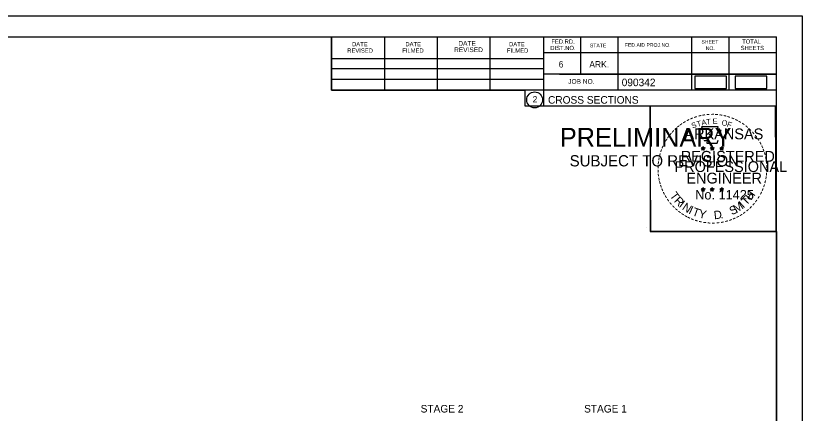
# Model space of a CAD drawing. Extents: x 1370515 to 1370849, y 383299 to 386073.
# Drawn here: x 1370703.4 to 1370848.7, y 385786 to 385859.5 of the extents above; entities that cross this region are included whole.
import ezdxf

# ---------------------------------------------------------------- set-up
doc = ezdxf.new("R2010")
doc.units = 0
for name, color, linetype in [('R_Axis Annot', 7, 'Continuous'), ('R_Border', 7, 'Continuous'), ('R_Border PE', 7, 'Continuous'), ('R_Border Prem', 7, 'Continuous'), ('R_Detour', 7, 'Continuous'), ('R_No Plot', 7, 'Continuous')]:
    doc.layers.add(name, color=color, linetype=linetype)

msp = doc.modelspace()

# ---------------------------------------------------------------- linework, layer by layer
at = {"layer": 'R_Border'}
for p, q in [((1370527.8, 385855.59), (1370843.98, 385855.59)), ((1370761.72, 385845.71), (1370761.72, 385855.59)), ((1370771.58, 385845.71), (1370771.58, 385855.39)), ((1370781.34, 385845.71), (1370781.34, 385855.39)), ((1370791.02, 385845.71), (1370791.02, 385855.39)), ((1370800.88, 385855.59), (1370800.88, 385842.79)), ((1370807.72, 385855.59), (1370807.72, 385848.65)), ((1370814.66, 385855.59), (1370814.66, 385845.71)), ((1370828.24, 385855.59), (1370828.24, 385845.71)), ((1370835.18, 385855.59), (1370835.18, 385845.71)), ((1370843.98, 385650.13), (1370843.98, 385855.59)), ((1370843.98, 385852.65), (1370800.88, 385852.65)), ((1370843.98, 385852.67), (1370843.98, 385852.67)), ((1370761.72, 385851.57), (1370800.88, 385851.57)), ((1370761.72, 385849.71), (1370800.88, 385849.71)), ((1370843.98, 385848.65), (1370800.88, 385848.65)), ((1370803.84, 385848.65), (1370843.98, 385848.65)), ((1370761.72, 385845.71), (1370761.72, 385847.77)), ((1370761.72, 385847.77), (1370800.88, 385847.77)), ((1370843.98, 385845.71), (1370761.72, 385845.71)), ((1370800.88, 385842.79), (1370843.98, 385842.79))]:
    msp.add_line(p, q, dxfattribs=at)
msp.add_circle((1370799.27, 385843.92), 1.47, dxfattribs=at)
at = {"layer": 'R_Border PE'}
for p, q in [((1370830.07, 385835.04), (1370830.42, 385834.93)), ((1370830.07, 385835.04), (1370830.32, 385835)), ((1370830.07, 385835.04), (1370830.3, 385834.92)), ((1370830.2, 385834.63), (1370830.42, 385834.93)), ((1370830.2, 385834.63), (1370830.33, 385834.88)), ((1370830.2, 385834.63), (1370830.41, 385834.85)), ((1370830.42, 385835.3), (1370830.37, 385835.04)), ((1370830.63, 385834.63), (1370830.41, 385834.85)), ((1370830.42, 385834.93), (1370830.42, 385835.3)), ((1370830.42, 385835.3), (1370830.46, 385835.05)), ((1370830.76, 385835.04), (1370830.42, 385834.93)), ((1370830.63, 385834.63), (1370830.42, 385834.93)), ((1370830.76, 385835.04), (1370830.48, 385834.99)), ((1370830.63, 385834.63), (1370830.49, 385834.92)), ((1370830.76, 385835.04), (1370830.56, 385834.94)), ((1370831.74, 385835.04), (1370832.09, 385834.93)), ((1370831.74, 385835.04), (1370831.99, 385835)), ((1370831.74, 385835.04), (1370831.97, 385834.92)), ((1370831.87, 385834.63), (1370832.09, 385834.93)), ((1370831.87, 385834.63), (1370832, 385834.88)), ((1370831.87, 385834.63), (1370832.08, 385834.85)), ((1370832.09, 385835.3), (1370832.04, 385835.04)), ((1370832.3, 385834.63), (1370832.08, 385834.85)), ((1370832.09, 385834.93), (1370832.09, 385835.3)), ((1370832.09, 385835.3), (1370832.13, 385835.05)), ((1370832.43, 385835.04), (1370832.09, 385834.93)), ((1370832.3, 385834.63), (1370832.09, 385834.93)), ((1370832.43, 385835.04), (1370832.15, 385834.99)), ((1370832.3, 385834.63), (1370832.16, 385834.92)), ((1370832.43, 385835.04), (1370832.23, 385834.94)), ((1370833.5, 385835.03), (1370833.85, 385834.92)), ((1370833.5, 385835.03), (1370833.75, 385834.98)), ((1370833.5, 385835.03), (1370833.74, 385834.91)), ((1370833.63, 385834.62), (1370833.85, 385834.92)), ((1370833.63, 385834.62), (1370833.76, 385834.87)), ((1370833.63, 385834.62), (1370833.85, 385834.84)), ((1370833.85, 385835.28), (1370833.81, 385835.03)), ((1370833.85, 385834.92), (1370833.85, 385835.28)), ((1370833.85, 385835.28), (1370833.9, 385835.03)), ((1370834.2, 385835.03), (1370833.85, 385834.92)), ((1370834.06, 385834.62), (1370833.85, 385834.92)), ((1370834.06, 385834.62), (1370833.85, 385834.84)), ((1370834.2, 385835.03), (1370833.91, 385834.98)), ((1370834.06, 385834.62), (1370833.93, 385834.91)), ((1370834.2, 385835.03), (1370833.99, 385834.93)), ((1370830.06, 385827.47), (1370830.41, 385827.36)), ((1370830.06, 385827.47), (1370830.32, 385827.42)), ((1370830.06, 385827.47), (1370830.3, 385827.35)), ((1370830.41, 385827.72), (1370830.37, 385827.47)), ((1370830.41, 385827.36), (1370830.41, 385827.72)), ((1370830.41, 385827.72), (1370830.46, 385827.47)), ((1370830.76, 385827.47), (1370830.41, 385827.36)), ((1370830.76, 385827.47), (1370830.47, 385827.42)), ((1370830.76, 385827.47), (1370830.55, 385827.37)), ((1370831.73, 385827.47), (1370832.08, 385827.36)), ((1370831.73, 385827.47), (1370831.98, 385827.42)), ((1370831.73, 385827.47), (1370831.97, 385827.35)), ((1370832.08, 385827.72), (1370832.04, 385827.47)), ((1370832.08, 385827.36), (1370832.08, 385827.72)), ((1370832.08, 385827.72), (1370832.13, 385827.47)), ((1370832.43, 385827.47), (1370832.08, 385827.36)), ((1370832.43, 385827.47), (1370832.14, 385827.42)), ((1370832.43, 385827.47), (1370832.22, 385827.37)), ((1370833.5, 385827.46), (1370833.85, 385827.35)), ((1370833.5, 385827.46), (1370833.75, 385827.41)), ((1370833.5, 385827.46), (1370833.74, 385827.34)), ((1370833.85, 385827.71), (1370833.81, 385827.46)), ((1370833.85, 385827.35), (1370833.85, 385827.71)), ((1370833.85, 385827.71), (1370833.9, 385827.46)), ((1370834.19, 385827.46), (1370833.85, 385827.35)), ((1370834.19, 385827.46), (1370833.91, 385827.41)), ((1370834.19, 385827.46), (1370833.99, 385827.36)), ((1370830.2, 385827.06), (1370830.41, 385827.36)), ((1370830.2, 385827.06), (1370830.32, 385827.3)), ((1370830.2, 385827.06), (1370830.41, 385827.28)), ((1370830.62, 385827.06), (1370830.41, 385827.36)), ((1370830.62, 385827.06), (1370830.41, 385827.27)), ((1370830.62, 385827.06), (1370830.49, 385827.35)), ((1370831.86, 385827.06), (1370832.08, 385827.36)), ((1370831.86, 385827.06), (1370831.99, 385827.3)), ((1370831.86, 385827.06), (1370832.08, 385827.28)), ((1370832.29, 385827.06), (1370832.08, 385827.36)), ((1370832.29, 385827.06), (1370832.08, 385827.27)), ((1370832.29, 385827.06), (1370832.16, 385827.35)), ((1370833.63, 385827.05), (1370833.85, 385827.35)), ((1370833.63, 385827.05), (1370833.76, 385827.29)), ((1370833.63, 385827.05), (1370833.85, 385827.27)), ((1370834.06, 385827.05), (1370833.85, 385827.35)), ((1370834.06, 385827.05), (1370833.85, 385827.26)), ((1370834.06, 385827.05), (1370833.92, 385827.34))]:
    msp.add_line(p, q, dxfattribs=at)
for points in [[(1370830.11, 385838.92), (1370830.38, 385838.09)], [(1370833.62, 385838), (1370833.76, 385838.28), (1370833.08, 385838.26), (1370833.22, 385838.92), (1370830.11, 385838.92)], [(1370830.6, 385836.5), (1370830.6, 385836.41), (1370831.16, 385836.39), (1370831.11, 385835.92), (1370832.98, 385835.92), (1370833.18, 385836.45)], [(1370830.42, 385835.3), (1370830.63, 385834.63), (1370830.07, 385835.04), (1370830.76, 385835.04), (1370830.2, 385834.63), (1370830.42, 385835.3)], [(1370832.09, 385835.3), (1370832.3, 385834.63), (1370831.74, 385835.04), (1370832.43, 385835.04), (1370831.87, 385834.63), (1370832.09, 385835.3)], [(1370833.85, 385835.28), (1370834.06, 385834.62), (1370833.5, 385835.03), (1370834.2, 385835.03), (1370833.63, 385834.62), (1370833.85, 385835.28)], [(1370830.41, 385827.72), (1370830.62, 385827.06), (1370830.06, 385827.47), (1370830.76, 385827.47), (1370830.2, 385827.06), (1370830.41, 385827.72)], [(1370832.08, 385827.72), (1370832.29, 385827.06), (1370831.73, 385827.47), (1370832.43, 385827.47), (1370831.86, 385827.06), (1370832.08, 385827.72)], [(1370833.85, 385827.71), (1370834.06, 385827.05), (1370833.5, 385827.46), (1370834.19, 385827.46), (1370833.63, 385827.05), (1370833.85, 385827.71)]]:
    msp.add_lwpolyline(points, dxfattribs=at)
for centre, radius in [((1370830.41, 385834.93), 0.172), ((1370830.41, 385834.93), 0.145), ((1370830.41, 385834.93), 0.116), ((1370830.41, 385834.93), 0.0991), ((1370830.41, 385834.93), 0.0747), ((1370830.41, 385834.93), 0.0495), ((1370830.41, 385834.93), 0.0296), ((1370832.08, 385834.93), 0.172), ((1370832.08, 385834.93), 0.145), ((1370832.08, 385834.93), 0.116), ((1370832.08, 385834.93), 0.0991), ((1370832.08, 385834.93), 0.0747), ((1370832.08, 385834.93), 0.0495), ((1370832.08, 385834.93), 0.0296), ((1370833.85, 385834.92), 0.172), ((1370833.85, 385834.92), 0.145), ((1370833.85, 385834.92), 0.116), ((1370833.85, 385834.92), 0.0991), ((1370833.85, 385834.92), 0.0747), ((1370833.85, 385834.92), 0.0495), ((1370833.85, 385834.92), 0.0296), ((1370830.41, 385827.36), 0.172), ((1370830.41, 385827.36), 0.145), ((1370830.41, 385827.36), 0.116), ((1370830.41, 385827.36), 0.0991), ((1370832.08, 385827.36), 0.172), ((1370832.08, 385827.36), 0.145), ((1370832.08, 385827.36), 0.116), ((1370832.08, 385827.36), 0.0991), ((1370833.85, 385827.35), 0.172), ((1370833.85, 385827.35), 0.145), ((1370833.85, 385827.35), 0.116), ((1370833.85, 385827.35), 0.0991), ((1370830.41, 385827.36), 0.0747), ((1370830.41, 385827.36), 0.0495), ((1370830.41, 385827.36), 0.0296), ((1370832.08, 385827.36), 0.0747), ((1370832.08, 385827.36), 0.0495), ((1370832.08, 385827.36), 0.0296), ((1370833.85, 385827.35), 0.0747), ((1370833.85, 385827.35), 0.0495), ((1370833.85, 385827.35), 0.0296)]:
    msp.add_circle(centre, radius, dxfattribs=at)
at = {"layer": 'R_Detour'}
for points in [[(1370828.87, 385846.02), (1370834.7, 385846.02), (1370834.7, 385848.33), (1370828.87, 385848.33)], [(1370836.36, 385846.02), (1370842.19, 385846.02), (1370842.19, 385848.33), (1370836.36, 385848.33)]]:
    msp.add_lwpolyline(points, close=True, dxfattribs=at)
at = {"layer": 'R_No Plot'}
for p, q in [((1370515.4, 385859.48), (1370848.73, 385859.48)), ((1370820.02, 385820.33), (1370820.02, 385820.33))]:
    msp.add_line(p, q, dxfattribs=at)
for points in [[(1370515.39, 385859.48), (1370848.73, 385859.48), (1370848.73, 385646.14), (1370515.39, 385646.14)], [(1370761.72, 385855.59), (1370761.72, 385845.71), (1370797.45, 385845.71), (1370797.45, 385842.79), (1370820.65, 385842.79), (1370820.65, 385819.57), (1370843.98, 385819.57), (1370843.98, 385650.13), (1370527.8, 385650.13), (1370527.8, 385855.59)], [(1370820.65, 385842.82), (1370843.75, 385842.82), (1370843.87, 385819.57), (1370820.77, 385819.57)]]:
    msp.add_lwpolyline(points, close=True, dxfattribs=at)

# ---------------------------------------------------------------- texts
at = {"layer": 'R_Axis Annot'}
for s, p in [('STAGE 2', (1370778.2, 385786.11)), ('STAGE 1', (1370808.41, 385786.11))]:
    msp.add_text(s, height=1.4, dxfattribs=at).set_placement(p)
at = {"layer": 'R_Border'}
for s, height, p in [('FED.RD.', 0.782, (1370802.36, 385854.31)), ('TOTAL', 0.782, (1370837.62, 385854.31)), ('DATE', 0.782, (1370765.52, 385853.83)), ('DATE', 0.782, (1370775.38, 385853.83)), ('REVISED', 0.879, (1370784.38, 385852.75)), ('DATE', 0.879, (1370785.16, 385853.93)), ('DATE', 0.782, (1370794.54, 385853.83)), ('DIST.NO.', 0.782, (1370802.16, 385853.13)), ('STATE', 0.684, (1370809.48, 385853.63)), ('FED.AID PROJ.NO.', 0.684, (1370815.94, 385853.73)), ('SHEET', 0.684, (1370830.1, 385854.31)), ('NO.', 0.684, (1370830.88, 385853.13)), ('SHEETS', 0.782, (1370837.34, 385853.13)), ('REVISED', 0.782, (1370764.64, 385852.65)), ('FILMED', 0.782, (1370774.8, 385852.65)), ('FILMED', 0.782, (1370794.14, 385852.65)), ('6', 1.17, (1370803.72, 385849.91)), ('ARK.', 1.172, (1370809.38, 385849.91)), ('090342', 1.4, (1370815.36, 385846.45)), ('JOB NO.', 0.879, (1370805.48, 385846.89)), ('2', 1.17, (1370798.89, 385843.44)), ('CROSS SECTIONS', 1.4, (1370801.74, 385843.22))]:
    msp.add_text(s, height=height, rotation=360, dxfattribs=at).set_placement(p)
at = {"layer": 'R_Border PE'}
for s, height, rotation, p in [('-', 1.6, 24.3072, (1370828.22, 385839.78)), ('-', 1.6, 19.1761, (1370828.86, 385840.05)), ('-', 1.6, 13.6301, (1370829.61, 385840.29)), ('-', 1.6, 10.2193, (1370830.28, 385840.45)), ('-', 1.6, 5.8968, (1370831.01, 385840.56)), ('-', 1.6, 0.1862, (1370831.78, 385840.63)), ('-', 1.6, 357.743, (1370832.51, 385840.62)), ('-', 1.6, 352.1617, (1370833.25, 385840.56)), ('-', 1.6, 347.2049, (1370833.97, 385840.45)), ('-', 1.6, 342.3362, (1370834.61, 385840.29)), ('-', 1.6, 337.8551, (1370835.34, 385840.07)), ('-', 1.6, 38.9507, (1370825.94, 385838.32)), ('-', 1.6, 36.2317, (1370826.41, 385838.7)), ('-', 1.6, 34.0636, (1370826.99, 385839.09)), ('-', 1.6, 28.7918, (1370827.59, 385839.46)), ('S', 1, 21.594, (1370828.46, 385838.6)), ('T', 1, 16.4036, (1370829.38, 385838.93)), ('A', 1, 11.2132, (1370830.2, 385839.18)), ('T', 1, 6.0228, (1370831.05, 385839.35)), ('E', 1, 0.8323, (1370832.16, 385839.46)), ('O', 1, 350.4515, (1370833.76, 385839.25)), ('F', 1, 340.0707, (1370834.71, 385839.02)), ('-', 1.6, 334.1211, (1370835.97, 385839.8)), ('-', 1.6, 329.6409, (1370836.55, 385839.52)), ('-', 1.6, 325.8627, (1370837.19, 385839.16)), ('-', 1.6, 320.5297, (1370837.8, 385838.73)), ('-', 1.6, 50.6142, (1370824.65, 385836.94)), ('-', 1.6, 48.423, (1370825.06, 385837.42)), ('-', 1.6, 42.9622, (1370825.5, 385837.9)), ('ARKANSAS', 2, 360, (1370826.96, 385836.63)), ('-', 1.6, 315.5786, (1370838.4, 385838.24)), ('-', 1.6, 309.8797, (1370838.97, 385837.69)), ('-', 1.6, 58.0706, (1370823.92, 385835.84)), ('-', 1.6, 54.2325, (1370824.24, 385836.37)), ('-', 1.6, 306.6522, (1370839.5, 385837.09)), ('-', 1.4, 303.6753, (1370839.98, 385836.52)), ('-', 1.6, 299.6684, (1370840.3, 385835.91)), ('-', 1.6, 72.3945, (1370823.12, 385833.99)), ('-', 1.6, 67.7743, (1370823.34, 385834.62)), ('-', 1.6, 62.8713, (1370823.6, 385835.23)), ('DWB', 0.01, 360, (1370830.4, 385834.93)), ('DWB', 0.01, 360, (1370832.07, 385834.93)), ('DWB', 0.01, 360, (1370833.84, 385834.91)), ('-', 1.6, 294.6628, (1370840.63, 385835.3)), ('-', 1.6, 290.5728, (1370840.88, 385834.73)), ('-', 1.6, 81.2013, (1370822.8, 385832.56)), ('-', 1.6, 75.461, (1370822.93, 385833.27)), ('REGISTERED', 2, 360, (1370826.28, 385832.48)), ('-', 1.6, 285.1233, (1370841.12, 385834.15)), ('-', 1.6, 280.5493, (1370841.32, 385833.4)), ('-', 1.6, 85.1863, (1370822.72, 385831.87)), ('PROFESSIONAL', 2, 360, (1370825.13, 385830.58)), ('-', 1.6, 276.5962, (1370841.48, 385832.64)), ('-', 1.6, 274.3301, (1370841.54, 385831.91)), ('-', 1.6, 94.1959, (1370822.73, 385830.44)), ('-', 1.6, 89.0622, (1370822.69, 385831.17)), ('ENGINEER', 2, 360, (1370827.32, 385828.45)), ('-', 1.6, 263.5172, (1370841.55, 385830.62)), ('-', 1.6, 269.9407, (1370841.57, 385831.28)), ('-', 1.6, 98.9479, (1370822.8, 385829.78)), ('-', 1.6, 101.7149, (1370822.94, 385829.04)), ('-', 1.6, 105.4578, (1370823.1, 385828.45)), ('-', 1.6, 255.7626, (1370841.37, 385829.28)), ('-', 1.6, 260.9953, (1370841.48, 385829.96)), ('-', 1.6, 109.0874, (1370823.31, 385827.82)), ('-', 1.6, 114.0643, (1370823.57, 385827.22)), ('-', 1.6, 247.8887, (1370840.97, 385827.89)), ('-', 1.6, 252.8681, (1370841.19, 385828.56)), ('-', 1.6, 115.7288, (1370823.87, 385826.6)), ('-', 1.6, 120.4471, (1370824.23, 385826.02)), ('T', 1.54, 306.0406, (1370824.17, 385826.2)), ('R', 1.54, 314.005, (1370824.93, 385825.15)), ('No. 11425', 1.757, 360, (1370828.95, 385825.5)), ('DWB', 0.01, 360, (1370830.4, 385827.35)), ('DWB', 0.01, 360, (1370832.07, 385827.35)), ('DWB', 0.01, 360, (1370833.83, 385827.34)), ('T', 1.54, 46.6444, (1370838.4, 385824.29)), ('H', 1.54, 54.6088, (1370839.29, 385825.23)), ('-', 1.6, 239.0712, (1370840.31, 385826.51)), ('-', 1.6, 244.6197, (1370840.71, 385827.26)), ('-', 1.6, 125.8934, (1370824.63, 385825.46)), ('-', 1.6, 130.7181, (1370825.09, 385824.9)), ('I', 1.54, 321.9694, (1370825.83, 385824.22)), ('N', 1.54, 326.5002, (1370826.4, 385823.74)), ('M', 1.54, 32.6563, (1370836.56, 385822.96)), ('I', 1.54, 42.1136, (1370837.84, 385823.81)), ('-', 1.6, 231.2538, (1370839.48, 385825.29)), ('-', 1.6, 233.8452, (1370839.91, 385825.86)), ('-', 1.6, 134.2238, (1370825.61, 385824.36)), ('-', 1.6, 138.9338, (1370826.14, 385823.9)), ('-', 1.6, 144.6463, (1370826.69, 385823.49)), ('I', 1.54, 335.3603, (1370827.61, 385822.96)), ('T', 1.54, 339.8912, (1370828.27, 385822.63)), ('Y', 1.54, 347.8556, (1370829.49, 385822.19)), ('D', 1.54, 6.3969, (1370832.47, 385821.83)), ('S', 1.54, 26.9312, (1370835.72, 385822.56)), ('-', 1.6, 215.7363, (1370837.93, 385823.75)), ('-', 1.6, 221.0851, (1370838.48, 385824.22)), ('-', 1.6, 225.7653, (1370839, 385824.73)), ('-', 1.6, 148.0898, (1370827.25, 385823.12)), ('-', 1.6, 151.5704, (1370827.83, 385822.79)), ('-', 1.6, 154.6002, (1370828.35, 385822.55)), ('-', 1.6, 158.5612, (1370828.98, 385822.29)), ('-', 1.6, 162.7983, (1370829.67, 385822.08)), ('.', 1.54, 13.7642, (1370833.66, 385821.95)), ('-', 1.6, 195.4743, (1370834.92, 385822.18)), ('-', 1.6, 200.7184, (1370835.6, 385822.42)), ('-', 1.6, 204.2516, (1370836.21, 385822.69)), ('-', 1.6, 207.3568, (1370836.84, 385823.01)), ('-', 1.6, 212.2491, (1370837.4, 385823.36)), ('-', 1.6, 167.5555, (1370830.38, 385821.92)), ('-', 1.6, 173.1155, (1370831.15, 385821.81)), ('-', 1.6, 176.5183, (1370831.9, 385821.75)), ('-', 1.6, 181.5918, (1370832.64, 385821.77)), ('-', 1.6, 185.8167, (1370833.45, 385821.85)), ('-', 1.6, 191.2858, (1370834.19, 385821.98))]:
    msp.add_text(s, height=height, rotation=rotation, dxfattribs=at).set_placement(p)
at = {"layer": 'R_Border Prem'}
for s, height, p in [('PRELIMINARY', 3.5, (1370803.93, 385835.25)), ('DWB', 0.01, (1370804.68, 385837.1)), ('SUBJECT TO REVISION', 2.0751, (1370805.74, 385831.62))]:
    msp.add_text(s, height=height, rotation=360, dxfattribs=at).set_placement(p)

doc.saveas('drawing.dxf')
